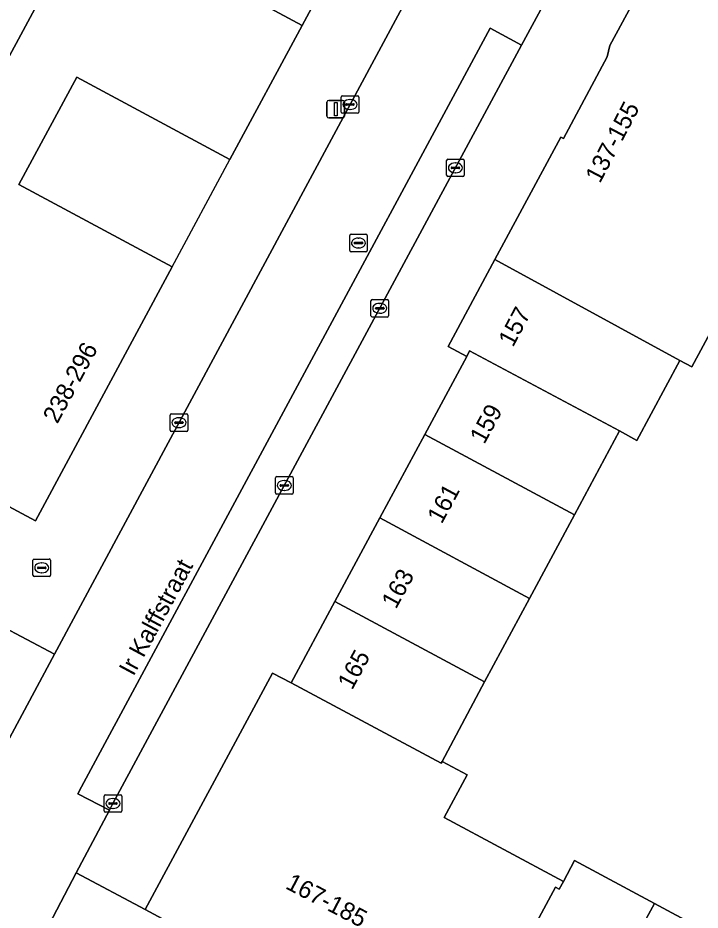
# Model space of a CAD drawing. Extents: x 159489 to 160304, y 383825 to 384531.
# Drawn here: x 159730.1 to 159768.9, y 384056.4 to 384107.2 of the extents above; entities that cross this region are included whole.
import ezdxf

# ---------------------------------------------------------------- set-up
doc = ezdxf.new("R2010")
doc.units = 0
for name, color, linetype in [('IMGEO_Brandkraan', 7, 'Continuous'), ('IMGEO_Erf', 7, 'Continuous'), ('IMGEO_Kolk', 7, 'Continuous'), ('IMGEO_Lichtmast', 7, 'Continuous'), ('IMGEO_Openbare_ruimte_label', 7, 'Continuous'), ('IMGEO_Pand', 7, 'Continuous'), ('IMGEO_Pand_nummerreeks', 7, 'Continuous'), ('IMGEO_Pand_overbouw', 7, 'Continuous'), ('IMGEO_Parkeervlak_gesloten', 7, 'Continuous'), ('IMGEO_Rijbaan_lokaal_gesloten', 7, 'Continuous'), ('IMGEO_Rioolput', 7, 'Continuous'), ('IMGEO_Voetpad_open', 7, 'Continuous')]:
    doc.layers.add(name, color=color, linetype=linetype)

msp = doc.modelspace()

# ---------------------------------------------------------------- linework, layer by layer
at = {"layer": 'IMGEO_Brandkraan'}
for p, q in [((159730.915, 384075.438), (159730.915, 384076.29)), ((159730.99, 384076.364), (159731.842, 384076.364)), ((159731.403, 384076.144), (159731.428, 384076.144)), ((159731.916, 384076.29), (159731.916, 384075.438)), ((159731.174, 384075.858), (159731.174, 384075.87)), ((159731.612, 384075.821), (159731.214, 384075.821)), ((159731.217, 384075.907), (159731.615, 384075.907)), ((159731.426, 384075.584), (159731.401, 384075.584)), ((159731.658, 384075.87), (159731.658, 384075.858)), ((159731.842, 384075.364), (159730.99, 384075.364))]:
    msp.add_line(p, q, dxfattribs=at)
for points in [[(159730.915, 384075.438), (159730.915, 384076.29)], [(159730.99, 384076.364), (159731.842, 384076.364)], [(159731.916, 384076.29), (159731.916, 384075.438)], [(159731.842, 384075.364), (159730.99, 384075.364)]]:
    msp.add_lwpolyline(points, dxfattribs=at)
for centre, radius, start, end in [((159730.992, 384076.288), 0.0765, 91.552, 178.448), ((159730.992, 384076.288), 0.0765, 91.552, 178.448), ((159731.84, 384076.288), 0.0765, 1.552, 88.448), ((159731.84, 384076.288), 0.0765, 1.552, 88.448), ((159731.214, 384075.867), 0.0403, 85.8775, 175.7526), ((159731.211, 384075.857), 0.0366, 178.938, 274.7102), ((159731.615, 384075.864), 0.043, 264.8664, 352.4533), ((159731.619, 384075.869), 0.0386, 1.7309, 96.639), ((159730.992, 384075.44), 0.0765, 181.552, 268.448), ((159730.992, 384075.44), 0.0765, 181.552, 268.448), ((159731.84, 384075.44), 0.0765, 271.552, 358.448), ((159731.84, 384075.44), 0.0765, 271.552, 358.448)]:
    msp.add_arc(centre, radius, start, end, dxfattribs=at)
for centre, major_axis, ratio, start_param, end_param in [((159731.402, 384075.864), (-0.387, 0.002), 0.722429, 4.712389, 7.853982), ((159731.427, 384075.864), (-0.39, 0.002), 0.717154, 1.570796, 4.712389)]:
    msp.add_ellipse(centre, major_axis=major_axis, ratio=ratio, start_param=start_param, end_param=end_param, dxfattribs=at)
at = {"layer": 'IMGEO_Erf'}
msp.add_lwpolyline([(159771.882, 384093.775), (159768.398, 384087.297), (159767.715, 384087.664), (159765.263, 384083.106), (159764.285, 384083.651), (159761.719, 384078.881), (159759.162, 384074.125), (159756.604, 384069.369), (159754.192, 384064.841), (159755.61, 384064.079), (159754.307, 384061.657), (159761.088, 384058.01), (159761.728, 384059.201), (159766.267, 384056.759), (159771.029, 384054.198)], dxfattribs=at)
at = {"layer": 'IMGEO_Kolk'}
for p, q in [((159748.45, 384101.81), (159748.45, 384102.662)), ((159748.525, 384102.736), (159749.377, 384102.736)), ((159748.938, 384102.516), (159748.963, 384102.516)), ((159749.451, 384102.662), (159749.451, 384101.81)), ((159748.709, 384102.23), (159748.709, 384102.242)), ((159749.147, 384102.193), (159748.749, 384102.193)), ((159748.752, 384102.279), (159749.15, 384102.279)), ((159748.961, 384101.956), (159748.936, 384101.956)), ((159749.193, 384102.242), (159749.193, 384102.23)), ((159749.377, 384101.736), (159748.525, 384101.736)), ((159754.447, 384098.206), (159754.447, 384099.058)), ((159754.522, 384099.132), (159755.374, 384099.132)), ((159754.935, 384098.912), (159754.96, 384098.912)), ((159755.448, 384099.058), (159755.448, 384098.206)), ((159754.706, 384098.626), (159754.706, 384098.638)), ((159755.144, 384098.589), (159754.746, 384098.589)), ((159754.749, 384098.675), (159755.147, 384098.675)), ((159755.19, 384098.638), (159755.19, 384098.626)), ((159755.374, 384098.132), (159754.522, 384098.132)), ((159754.958, 384098.352), (159754.933, 384098.352)), ((159750.143, 384090.212), (159750.143, 384091.064)), ((159750.218, 384091.138), (159751.07, 384091.138)), ((159750.631, 384090.918), (159750.656, 384090.918)), ((159751.144, 384091.064), (159751.144, 384090.212)), ((159750.402, 384090.632), (159750.402, 384090.644)), ((159750.84, 384090.595), (159750.442, 384090.595)), ((159750.445, 384090.681), (159750.843, 384090.681)), ((159750.654, 384090.358), (159750.629, 384090.358)), ((159750.886, 384090.644), (159750.886, 384090.632)), ((159751.07, 384090.138), (159750.218, 384090.138)), ((159738.72, 384083.702), (159738.72, 384084.554)), ((159738.795, 384084.628), (159739.647, 384084.628)), ((159739.022, 384084.171), (159739.42, 384084.171)), ((159739.208, 384084.408), (159739.233, 384084.408)), ((159739.721, 384084.554), (159739.721, 384083.702)), ((159738.979, 384084.122), (159738.979, 384084.134)), ((159739.417, 384084.085), (159739.019, 384084.085)), ((159739.231, 384083.848), (159739.206, 384083.848)), ((159739.463, 384084.134), (159739.463, 384084.122)), ((159739.647, 384083.628), (159738.795, 384083.628)), ((159744.713, 384080.126), (159744.713, 384080.978)), ((159744.788, 384081.052), (159745.64, 384081.052)), ((159745.201, 384080.832), (159745.226, 384080.832)), ((159745.714, 384080.978), (159745.714, 384080.126)), ((159744.972, 384080.546), (159744.972, 384080.558)), ((159745.41, 384080.509), (159745.012, 384080.509)), ((159745.015, 384080.595), (159745.413, 384080.595)), ((159745.224, 384080.272), (159745.199, 384080.272)), ((159745.456, 384080.558), (159745.456, 384080.546)), ((159745.64, 384080.052), (159744.788, 384080.052)), ((159734.964, 384062.019), (159734.964, 384062.871)), ((159735.039, 384062.945), (159735.891, 384062.945)), ((159735.965, 384062.871), (159735.965, 384062.019)), ((159735.223, 384062.439), (159735.223, 384062.451)), ((159735.661, 384062.402), (159735.263, 384062.402)), ((159735.266, 384062.488), (159735.664, 384062.488)), ((159735.452, 384062.725), (159735.477, 384062.725)), ((159735.707, 384062.451), (159735.707, 384062.439)), ((159735.891, 384061.945), (159735.039, 384061.945)), ((159735.475, 384062.165), (159735.45, 384062.165))]:
    msp.add_line(p, q, dxfattribs=at)
for points in [[(159748.45, 384101.81), (159748.45, 384102.662)], [(159748.525, 384102.736), (159749.377, 384102.736)], [(159749.451, 384102.662), (159749.451, 384101.81)], [(159749.377, 384101.736), (159748.525, 384101.736)], [(159754.447, 384098.206), (159754.447, 384099.058)], [(159754.522, 384099.132), (159755.374, 384099.132)], [(159755.448, 384099.058), (159755.448, 384098.206)], [(159755.374, 384098.132), (159754.522, 384098.132)], [(159750.143, 384090.212), (159750.143, 384091.064)], [(159750.218, 384091.138), (159751.07, 384091.138)], [(159751.144, 384091.064), (159751.144, 384090.212)], [(159751.07, 384090.138), (159750.218, 384090.138)], [(159738.72, 384083.702), (159738.72, 384084.554)], [(159738.795, 384084.628), (159739.647, 384084.628)], [(159739.721, 384084.554), (159739.721, 384083.702)], [(159739.647, 384083.628), (159738.795, 384083.628)], [(159744.713, 384080.126), (159744.713, 384080.978)], [(159744.788, 384081.052), (159745.64, 384081.052)], [(159745.714, 384080.978), (159745.714, 384080.126)], [(159745.64, 384080.052), (159744.788, 384080.052)], [(159734.964, 384062.019), (159734.964, 384062.871)], [(159735.039, 384062.945), (159735.891, 384062.945)], [(159735.965, 384062.871), (159735.965, 384062.019)], [(159735.891, 384061.945), (159735.039, 384061.945)]]:
    msp.add_lwpolyline(points, dxfattribs=at)
for centre, radius, start, end in [((159748.527, 384102.66), 0.0765, 91.552, 178.448), ((159748.527, 384102.66), 0.0765, 91.552, 178.448), ((159749.375, 384102.66), 0.0765, 1.552, 88.448), ((159749.375, 384102.66), 0.0765, 1.552, 88.448), ((159748.749, 384102.239), 0.0403, 85.8775, 175.7526), ((159748.746, 384102.229), 0.0366, 178.938, 274.7102), ((159749.15, 384102.236), 0.043, 264.8664, 352.4533), ((159749.154, 384102.241), 0.0386, 1.7309, 96.639), ((159748.527, 384101.812), 0.0765, 181.552, 268.448), ((159748.527, 384101.812), 0.0765, 181.552, 268.448), ((159749.375, 384101.812), 0.0765, 271.552, 358.448), ((159749.375, 384101.812), 0.0765, 271.552, 358.448), ((159754.524, 384099.056), 0.0765, 91.552, 178.448), ((159754.524, 384099.056), 0.0765, 91.552, 178.448), ((159755.372, 384099.056), 0.0765, 1.552, 88.448), ((159755.372, 384099.056), 0.0765, 1.552, 88.448), ((159754.746, 384098.635), 0.0403, 85.8775, 175.7526), ((159754.743, 384098.625), 0.0366, 178.938, 274.7102), ((159755.147, 384098.632), 0.043, 264.8664, 352.4533), ((159755.151, 384098.637), 0.0386, 1.7309, 96.639), ((159754.524, 384098.208), 0.0765, 181.552, 268.448), ((159754.524, 384098.208), 0.0765, 181.552, 268.448), ((159755.372, 384098.208), 0.0765, 271.552, 358.448), ((159755.372, 384098.208), 0.0765, 271.552, 358.448), ((159750.22, 384091.062), 0.0765, 91.552, 178.448), ((159750.22, 384091.062), 0.0765, 91.552, 178.448), ((159751.068, 384091.062), 0.0765, 1.552, 88.448), ((159751.068, 384091.062), 0.0765, 1.552, 88.448), ((159750.442, 384090.641), 0.0403, 85.8775, 175.7526), ((159750.439, 384090.631), 0.0366, 178.938, 274.7102), ((159750.843, 384090.638), 0.043, 264.8664, 352.4533), ((159750.847, 384090.643), 0.0386, 1.7309, 96.639), ((159750.22, 384090.214), 0.0765, 181.552, 268.448), ((159750.22, 384090.214), 0.0765, 181.552, 268.448), ((159751.068, 384090.214), 0.0765, 271.552, 358.448), ((159751.068, 384090.214), 0.0765, 271.552, 358.448), ((159738.797, 384084.552), 0.0765, 91.552, 178.448), ((159738.797, 384084.552), 0.0765, 91.552, 178.448), ((159739.019, 384084.131), 0.0403, 85.8775, 175.7526), ((159739.424, 384084.133), 0.0386, 1.7309, 96.639), ((159739.645, 384084.552), 0.0765, 1.552, 88.448), ((159739.645, 384084.552), 0.0765, 1.552, 88.448), ((159738.797, 384083.704), 0.0765, 181.552, 268.448), ((159738.797, 384083.704), 0.0765, 181.552, 268.448), ((159739.016, 384084.121), 0.0366, 178.938, 274.7102), ((159739.42, 384084.128), 0.043, 264.8664, 352.4533), ((159739.645, 384083.704), 0.0765, 271.552, 358.448), ((159739.645, 384083.704), 0.0765, 271.552, 358.448), ((159744.79, 384080.976), 0.0765, 91.552, 178.448), ((159744.79, 384080.976), 0.0765, 91.552, 178.448), ((159745.638, 384080.976), 0.0765, 1.552, 88.448), ((159745.638, 384080.976), 0.0765, 1.552, 88.448), ((159744.79, 384080.128), 0.0765, 181.552, 268.448), ((159744.79, 384080.128), 0.0765, 181.552, 268.448), ((159745.012, 384080.555), 0.0403, 85.8775, 175.7526), ((159745.009, 384080.545), 0.0366, 178.938, 274.7102), ((159745.413, 384080.552), 0.043, 264.8664, 352.4533), ((159745.417, 384080.557), 0.0386, 1.7309, 96.639), ((159745.638, 384080.128), 0.0765, 271.552, 358.448), ((159745.638, 384080.128), 0.0765, 271.552, 358.448), ((159735.041, 384062.869), 0.0765, 91.552, 178.448), ((159735.041, 384062.869), 0.0765, 91.552, 178.448), ((159735.889, 384062.869), 0.0765, 1.552, 88.448), ((159735.889, 384062.869), 0.0765, 1.552, 88.448), ((159735.263, 384062.448), 0.0403, 85.8775, 175.7526), ((159735.26, 384062.438), 0.0366, 178.938, 274.7102), ((159735.664, 384062.445), 0.043, 264.8664, 352.4533), ((159735.668, 384062.45), 0.0386, 1.7309, 96.639), ((159735.041, 384062.021), 0.0765, 181.552, 268.448), ((159735.041, 384062.021), 0.0765, 181.552, 268.448), ((159735.889, 384062.021), 0.0765, 271.552, 358.448), ((159735.889, 384062.021), 0.0765, 271.552, 358.448)]:
    msp.add_arc(centre, radius, start, end, dxfattribs=at)
for centre, major_axis, ratio, start_param, end_param in [((159748.937, 384102.236), (-0.387, 0.002), 0.722429, 4.712389, 7.853982), ((159748.962, 384102.236), (-0.39, 0.002), 0.717154, 1.570796, 4.712389), ((159754.934, 384098.632), (-0.387, 0.002), 0.722429, 4.712389, 7.853982), ((159754.959, 384098.632), (-0.39, 0.002), 0.717154, 1.570796, 4.712389), ((159750.63, 384090.638), (-0.387, 0.002), 0.722429, 4.712389, 7.853982), ((159750.655, 384090.638), (-0.39, 0.002), 0.717154, 1.570796, 4.712389), ((159739.207, 384084.128), (-0.387, 0.002), 0.722429, 4.712389, 7.853982), ((159739.232, 384084.128), (-0.39, 0.002), 0.717154, 1.570796, 4.712389), ((159745.2, 384080.552), (-0.387, 0.002), 0.722429, 4.712389, 7.853982), ((159745.225, 384080.552), (-0.39, 0.002), 0.717154, 1.570796, 4.712389), ((159735.451, 384062.445), (-0.387, 0.002), 0.722429, 4.712389, 7.853982), ((159735.476, 384062.445), (-0.39, 0.002), 0.717154, 1.570796, 4.712389)]:
    msp.add_ellipse(centre, major_axis=major_axis, ratio=ratio, start_param=start_param, end_param=end_param, dxfattribs=at)
at = {"layer": 'IMGEO_Lichtmast'}
for p, q in [((159747.741, 384102.475), (159748.531, 384102.475)), ((159748.531, 384102.475), (159747.741, 384102.475)), ((159747.641, 384101.575), (159747.641, 384102.375)), ((159747.641, 384102.375), (159747.641, 384101.575)), ((159748.631, 384102.375), (159748.631, 384101.575)), ((159748.631, 384101.575), (159748.631, 384102.375)), ((159748.531, 384101.475), (159747.741, 384101.475)), ((159747.741, 384101.475), (159748.531, 384101.475))]:
    msp.add_line(p, q, dxfattribs=at)
msp.add_lwpolyline([(159748.061, 384102.35), (159748.211, 384102.35), (159748.211, 384101.6), (159748.061, 384101.6), (159748.061, 384102.35)], dxfattribs=at)
for centre, start, end in [((159747.741, 384102.375), 90, 180), ((159747.741, 384102.375), 90, 180), ((159748.531, 384102.375), 0, 90), ((159748.531, 384102.375), 360, 90), ((159747.741, 384101.575), 180, 270), ((159747.741, 384101.575), 180, 270), ((159748.531, 384101.575), 270, 0), ((159748.531, 384101.575), 270, 0)]:
    msp.add_arc(centre, 0.1, start, end, dxfattribs=at)
at = {"layer": 'IMGEO_Pand'}
for points in [[(159706.87, 384112.163), (159701.898, 384102.938), (159698.331, 384104.838), (159694.71, 384098.068), (159731.054, 384078.532), (159738.835, 384092.992), (159730.115, 384097.685), (159733.403, 384103.792), (159742.122, 384099.1), (159746.233, 384106.739), (159734.04, 384113.305), (159727.463, 384101.093)], [(159780.079, 384103.825), (159766.66, 384111.026), (159765.061, 384108.041), (159763.74, 384105.588), (159763.585, 384104.945), (159761.091, 384100.297), (159760.941, 384100.377), (159757.19, 384093.409), (159767.715, 384087.664), (159768.398, 384087.297), (159771.882, 384093.775), (159773.584, 384092.86), (159774.052, 384092.608), (159774.383, 384093.224)], [(159757.19, 384093.409), (159754.532, 384088.469), (159755.588, 384087.9), (159755.752, 384088.221), (159764.285, 384083.651), (159765.263, 384083.106), (159767.715, 384087.664)], [(159761.719, 384078.881), (159764.285, 384083.651), (159755.752, 384088.221), (159755.588, 384087.9), (159753.203, 384083.461)], [(159759.162, 384074.125), (159761.719, 384078.881), (159753.203, 384083.461), (159750.647, 384078.705)], [(159759.162, 384074.125), (159750.647, 384078.705), (159748.091, 384073.948), (159756.604, 384069.369)], [(159745.606, 384069.324), (159754.136, 384064.736), (159754.192, 384064.841), (159756.604, 384069.369), (159748.091, 384073.948)], [(159745.606, 384069.324), (159744.543, 384069.861), (159737.293, 384056.412), (159744, 384052.814), (159744.059, 384052.782), (159745.177, 384054.872), (159748.885, 384052.879), (159747.763, 384050.791), (159747.838, 384050.751), (159754.877, 384046.966), (159760.634, 384057.677), (159760.847, 384057.561), (159761.088, 384058.01), (159754.307, 384061.657), (159755.61, 384064.079), (159754.192, 384064.841), (159754.136, 384064.736)], [(159765.389, 384055.118), (159766.267, 384056.759), (159761.728, 384059.201), (159761.088, 384058.01), (159760.847, 384057.561), (159760.634, 384057.677), (159754.877, 384046.966), (159759.654, 384044.398)], [(159770.147, 384052.559), (159771.029, 384054.198), (159766.267, 384056.759), (159765.389, 384055.118), (159759.654, 384044.398), (159764.388, 384041.852)]]:
    msp.add_lwpolyline(points, close=True, dxfattribs=at)
at = {"layer": 'IMGEO_Pand_overbouw'}
msp.add_lwpolyline([(159738.835, 384092.992), (159742.122, 384099.1), (159733.403, 384103.792), (159730.115, 384097.685)], close=True, dxfattribs=at)
at = {"layer": 'IMGEO_Parkeervlak_gesloten'}
msp.add_lwpolyline([(159758.71, 384105.618), (159756.933, 384106.574), (159733.684, 384063.394), (159733.476, 384062.998), (159735.26, 384062.057), (159735.465, 384062.445)], close=True, dxfattribs=at)
at = {"layer": 'IMGEO_Rijbaan_lokaal_gesloten'}
msp.add_lwpolyline([(159785.842, 384170.895), (159785.06, 384169.44), (159732.135, 384070.941), (159724.587, 384056.893), (159731.166, 384054.292), (159733.379, 384058.49), (159735.26, 384062.057), (159733.476, 384062.998), (159733.684, 384063.394), (159756.933, 384106.574), (159758.71, 384105.618), (159759.915, 384107.857), (159758.589, 384108.571)], dxfattribs=at)
at = {"layer": 'IMGEO_Rioolput'}
for p, q in [((159749.007, 384094.855), (159749.859, 384094.855)), ((159748.932, 384093.929), (159748.932, 384094.781)), ((159749.191, 384094.349), (159749.191, 384094.361)), ((159749.234, 384094.398), (159749.632, 384094.398)), ((159749.42, 384094.635), (159749.445, 384094.635)), ((159749.675, 384094.361), (159749.675, 384094.349)), ((159749.933, 384094.781), (159749.933, 384093.929)), ((159749.859, 384093.855), (159749.007, 384093.855)), ((159749.629, 384094.312), (159749.231, 384094.312)), ((159749.443, 384094.075), (159749.418, 384094.075))]:
    msp.add_line(p, q, dxfattribs=at)
for points in [[(159749.007, 384094.855), (159749.859, 384094.855)], [(159748.932, 384093.929), (159748.932, 384094.781)], [(159749.933, 384094.781), (159749.933, 384093.929)], [(159749.859, 384093.855), (159749.007, 384093.855)]]:
    msp.add_lwpolyline(points, dxfattribs=at)
for centre, radius, start, end in [((159749.009, 384094.779), 0.0765, 91.552, 178.448), ((159749.009, 384094.779), 0.0765, 91.552, 178.448), ((159749.857, 384094.779), 0.0765, 1.552, 88.448), ((159749.857, 384094.779), 0.0765, 1.552, 88.448), ((159749.231, 384094.358), 0.0403, 85.8775, 175.7526), ((159749.228, 384094.348), 0.0366, 178.938, 274.7102), ((159749.632, 384094.355), 0.043, 264.8664, 352.4533), ((159749.636, 384094.36), 0.0386, 1.7309, 96.639), ((159749.009, 384093.931), 0.0765, 181.552, 268.448), ((159749.009, 384093.931), 0.0765, 181.552, 268.448), ((159749.857, 384093.931), 0.0765, 271.552, 358.448), ((159749.857, 384093.931), 0.0765, 271.552, 358.448)]:
    msp.add_arc(centre, radius, start, end, dxfattribs=at)
for centre, major_axis, ratio, start_param, end_param in [((159749.419, 384094.355), (-0.387, 0.002), 0.722429, 4.712389, 7.853982), ((159749.444, 384094.355), (-0.39, 0.002), 0.717154, 1.570796, 4.712389)]:
    msp.add_ellipse(centre, major_axis=major_axis, ratio=ratio, start_param=start_param, end_param=end_param, dxfattribs=at)
at = {"layer": 'IMGEO_Voetpad_open'}
for points in [[(159785.06, 384169.44), (159781.081, 384171.509), (159772.985, 384156.701), (159771.281, 384156.067), (159769.847, 384153.424), (159770.883, 384152.856), (159759.218, 384131.522), (159756.188, 384125.276), (159748.367, 384110.748), (159746.233, 384106.739), (159742.122, 384099.1), (159733.403, 384103.792), (159730.115, 384097.685), (159738.835, 384092.992), (159731.054, 384078.532), (159694.71, 384098.068), (159691.579, 384099.696), (159688.581, 384094.024), (159727.344, 384073.348), (159727.4, 384073.454), (159732.135, 384070.941)], [(159748.885, 384052.879), (159745.177, 384054.872), (159744.059, 384052.782), (159744, 384052.814), (159737.293, 384056.412), (159733.379, 384058.49), (159731.166, 384054.292), (159797.098, 384018.803), (159799.393, 384023.037), (159796.313, 384024.693), (159790.874, 384027.608), (159790.367, 384028.077), (159785.732, 384030.559), (159785.645, 384030.424), (159778.666, 384034.176), (159773.904, 384036.736), (159769.137, 384039.299), (159764.388, 384041.852), (159759.654, 384044.398), (159754.877, 384046.966), (159747.838, 384050.751), (159747.763, 384050.791)]]:
    msp.add_lwpolyline(points, close=True, dxfattribs=at)
for points in [[(159709.034, 384132.721), (159691.579, 384099.696), (159694.71, 384098.068), (159698.331, 384104.838), (159701.898, 384102.938), (159706.87, 384112.163), (159727.463, 384101.093), (159734.04, 384113.305), (159746.233, 384106.739), (159748.367, 384110.748)], [(159750.647, 384078.705), (159753.203, 384083.461), (159755.588, 384087.9), (159754.532, 384088.469), (159757.19, 384093.409), (159760.941, 384100.377), (159761.091, 384100.297), (159763.585, 384104.945), (159763.74, 384105.588), (159765.061, 384108.041), (159766.66, 384111.026), (159768.446, 384114.365), (159768.611, 384114.673), (159768.906, 384114.514)], [(159758.589, 384108.571), (159759.915, 384107.857), (159758.71, 384105.618), (159735.465, 384062.445), (159735.26, 384062.057), (159733.379, 384058.49), (159737.293, 384056.412), (159744.543, 384069.861), (159745.606, 384069.324), (159748.091, 384073.948), (159750.647, 384078.705)], [(159720.003, 384056.911), (159724.587, 384056.893), (159732.135, 384070.941), (159727.4, 384073.454), (159727.344, 384073.348), (159723.965, 384067.013), (159726.26, 384065.693), (159723.307, 384060.146)]]:
    msp.add_lwpolyline(points, dxfattribs=at)

# ---------------------------------------------------------------- texts
at = {"layer": 'IMGEO_Openbare_ruimte_label'}
msp.add_text('Ir Kalffstraat', height=1, rotation=61.6915, dxfattribs=at).set_placement((159736.633, 384069.651))
at = {"layer": 'IMGEO_Pand_nummerreeks'}
for s, rotation, p in [('137-155', 62.2691, (159763.167, 384097.709)), ('157', 62.0949, (159758.221, 384088.38)), ('238-296', 61.7133, (159732.304, 384084.02)), ('159', 61.4491, (159756.589, 384082.854)), ('161', 61.5168, (159754.166, 384078.318)), ('163', 61.3028, (159751.565, 384073.474)), ('165', 61.7913, (159749.071, 384068.863)), ('167-185', 332.3598, (159745.224, 384057.636))]:
    msp.add_text(s, height=1, rotation=rotation, dxfattribs=at).set_placement(p)

doc.saveas('drawing.dxf')
